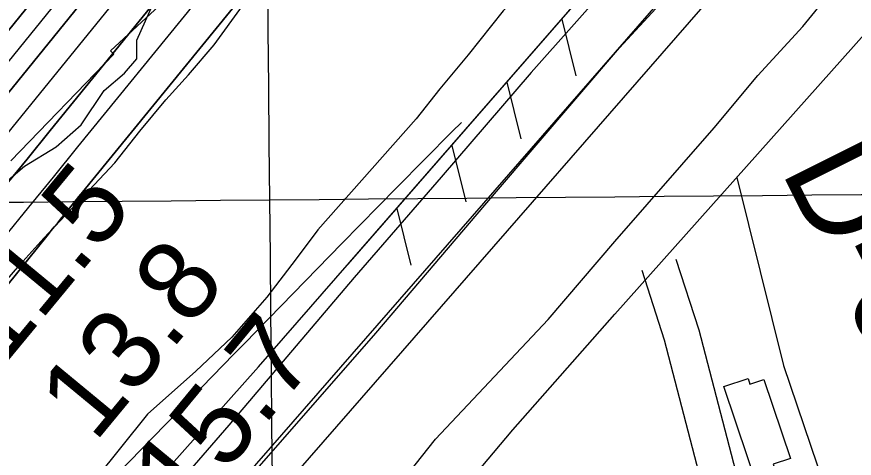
# Model space of a CAD drawing. Extents: x 3598634 to 3636690, y 517270 to 542944.
# Drawn here: x 3607864 to 3608565, y 528569 to 528938 of the extents above; entities that cross this region are included whole.
import ezdxf

# ---------------------------------------------------------------- set-up
doc = ezdxf.new("R2010")
doc.units = 0
for name, color, linetype in [('V-BLDG-OTLN', 7, 'Continuous'), ('V-FLOD-BASE', 7, 'Continuous'), ('V-GRID-MAJR', 7, 'Continuous'), ('V-LEVE-TOET', 7, 'Continuous'), ('V-RIVR-EDGE', 7, 'Continuous'), ('V-RIVR-RANG', 7, 'Continuous'), ('V-RIVR-RANG-IDEN', 7, 'Continuous'), ('V-ROAD-CNTR', 7, 'Continuous'), ('V-RRAP-FSHR', 7, 'Continuous'), ('V-RRAP-RVMT', 7, 'Continuous'), ('V-SITE-VEGE', 7, 'Continuous'), ('V-SURV-LINE', 7, 'Continuous'), ('V-TOPO-DPTH', 7, 'Continuous'), ('V-TOPO-MINR', 7, 'Continuous'), ('V-TOPO-WATR', 7, 'Continuous')]:
    doc.layers.add(name, color=color, linetype=linetype)

msp = doc.modelspace()

# ---------------------------------------------------------------- linework, layer by layer
at = {"layer": 'V-BLDG-OTLN'}
msp.add_lwpolyline([(3608489.164, 528634.588), (3608511.44, 528568.495), (3608496.877, 528563.586), (3608503.15, 528544.98), (3608485.9280000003, 528539.178), (3608455.8140000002, 528628.52), (3608475.948, 528635.307), (3608477.5130000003, 528630.662)], close=True, dxfattribs=at)
at = {"layer": 'V-FLOD-BASE'}
msp.add_lwpolyline([(3608057.5300000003, 528550.9130000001), (3608164.435, 528673.187), (3608262.2660000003, 528787.826), (3608368.484, 528912.1900000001), (3608466.29, 529018.471), (3608577.392, 529146.306), (3608670.332, 529256.082), (3608736.005, 529328.328), (3608865.98, 529479.787), (3608928.157, 529547.863), (3609005.674, 529621.468), (3609041.299, 529658.281), (3609167.019, 529783.983), (3609227.077, 529840.922)], dxfattribs=at)
at = {"layer": 'V-GRID-MAJR'}
for points in [[(3608130.468, 522726.087), (3608075.829, 528784.895), (3608021.174, 534845.634), (3607966.518, 540906.389), (3607966.501, 540908.307)], [(3602797.865, 528737.682), (3608075.829, 528784.895), (3613353.788, 528832.875), (3618631.739, 528881.623), (3623909.683, 528931.139), (3629187.62, 528981.4230000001), (3634465.549, 529032.474), (3634465.5500000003, 529032.474)]]:
    msp.add_spline(points, degree=3, dxfattribs=at)
at = {"layer": 'V-LEVE-TOET'}
for points in [[(3609179.066, 529856.382), (3609077.804, 529759.86), (3609000.984, 529686.253), (3608908.107, 529599.458), (3608868.9960000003, 529561.265), (3608835.45, 529520.268), (3608770.453, 529441.058), (3608694.98, 529351.427), (3608662.1380000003, 529313.215), (3608630.699, 529279.178), (3608596.457, 529238.185), (3608544.745, 529177.042), (3608478.363, 529100.621), (3608366.5670000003, 528972.789), (3608294.6, 528891.508), (3608219.131, 528803.968)], [(3608107.384, 528449.088), (3608214.329, 528584.594), (3608308.637, 528684.617), (3608364.539, 528749.925), (3608447.688, 528845.104), (3608484.0300000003, 528888.878), (3608521.756, 528929.863), (3608569.282, 528988.231), (3608667.838, 529113.314), (3608718.165, 529177.247), (3608772.665, 529239.076), (3608802.713, 529273.814), (3608860.69, 529334.24), (3608893.544, 529376.632), (3608927.0840000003, 529414.841), (3608971.796, 529463.4670000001), (3609015.1010000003, 529507.223), (3609104.504, 529597.509), (3609149.214, 529645.438), (3609180.649, 529678.081)], [(3608219.131, 528803.968), (3608146.46, 528719.902), (3608041.639, 528596.229), (3607974.559, 528519.112)]]:
    msp.add_lwpolyline(points, dxfattribs=at)
at = {"layer": 'V-RIVR-EDGE'}
for points in [[(3607896.9930070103, 528829.1822676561), (3607918.050327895, 528847.7403245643), (3607937.3319151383, 528876.5083251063), (3607954.176584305, 528890.8745122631), (3607964.4117631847, 528902.8557362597), (3607964.450358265, 528918.4641332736), (3607978.9382683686, 528950.8459469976), (3607989.1853226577, 528967.6297546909), (3608009.615600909, 528975.3834827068), (3608032.488734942, 528999.9403159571), (3608052.335018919, 529014.2990809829), (3608070.9569061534, 529019.0556474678), (3608083.6007990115, 529034.0325485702), (3608110.7118200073, 529072.9867419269), (3608141.995413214, 529099.9240850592), (3608192.621455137, 529180.2426701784), (3608231.143065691, 529220.969628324), (3608259.456217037, 529260.5211757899), (3608299.2096464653, 529313.8519472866), (3608325.735188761, 529358.8108546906)], [(3607634.578266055, 528557.2828526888), (3607647.8313884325, 528575.8602071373), (3607658.088833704, 528596.8462755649), (3607670.1294347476, 528610.6240151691), (3607695.3741721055, 528623.1684514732), (3607739.246734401, 528642.8707461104), (3607763.9104463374, 528663.220865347), (3607782.5872573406, 528690.1893814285), (3607813.9569472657, 528751.9454563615), (3607845.2717134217, 528791.489581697), (3607870.5387171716, 528813.0388624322), (3607896.9930070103, 528829.1822676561)]]:
    msp.add_lwpolyline(points, dxfattribs=at)
at = {"layer": 'V-ROAD-CNTR'}
for points in [[(3606832.73929598, 526952.0380697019), (3606973.781013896, 527100.24877328), (3607148.851663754, 527293.0463876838), (3607268.52342441, 527428.8341161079), (3607385.5411903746, 527558.818856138), (3607495.79796986, 527683.4706068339), (3607551.7768579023, 527751.395470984), (3607615.94772956, 527832.2103093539), (3607705.6035502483, 527929.2831152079), (3607806.918347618, 528046.9048799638), (3607941.5770783, 528200.235573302), (3608081.9227976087, 528357.7092583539), (3608279.135403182, 528592.4517888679), (3608364.492232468, 528689.307595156), (3608525.0129114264, 528869.3482350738), (3608605.4767504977, 528959.8330541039), (3608701.50055845, 529074.4648248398), (3608833.107295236, 529225.3725230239), (3608919.0001234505, 529316.1323415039), (3609050.5348603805, 529472.9320279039), (3609139.7006820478, 529575.1978233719), (3609208.81954381, 529647.870678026)], [(3608466.4920284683, 528803.7113663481), (3608505.692950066, 528646.338681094), (3608601.7287579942, 528362.269249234), (3608772.481416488, 527825.480322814)], [(3608415.530130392, 528735.1725034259), (3608434.6610921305, 528676.1496214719), (3608465.3830306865, 528557.9068579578), (3608506.948947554, 528426.4981207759), (3608525.973909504, 528355.965261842), (3608533.1488951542, 528306.5663606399), (3608536.582888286, 528256.783460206), (3608541.2408789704, 528212.94154789), (3608549.5638623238, 528173.7936261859), (3608569.869821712, 528109.3447550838), (3608666.4776284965, 527809.824354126), (3608789.826381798, 527407.3961589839), (3608865.133231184, 527174.4286249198), (3608901.88515768, 527053.927865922)], [(3608386.9921874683, 528725.9225219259), (3608405.8491497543, 528667.74563828), (3608436.5430883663, 528549.604874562), (3608478.15100515, 528418.0641376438), (3608496.541968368, 528349.8812740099), (3608503.296954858, 528303.372367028), (3608506.6929480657, 528254.165465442), (3608511.572938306, 528208.225557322), (3608520.517920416, 528166.149641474), (3608541.2878788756, 528100.2327733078), (3608637.859685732, 527800.8243721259), (3608761.21043903, 527398.3861770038), (3608836.511288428, 527165.4386429), (3608873.1892150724, 527045.175883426)]]:
    msp.add_lwpolyline(points, dxfattribs=at)
at = {"layer": 'V-RRAP-FSHR'}
for p, q in [((3608320.009321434, 528936.067101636), (3608331.7782978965, 528888.6761964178)), ((3608274.035413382, 528883.2812072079), (3608285.804389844, 528835.8893019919)), ((3608228.0615053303, 528830.4943127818), (3608239.830481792, 528783.103407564)), ((3608182.0875972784, 528777.7084183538), (3608193.85657374, 528730.317513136))]:
    msp.add_line(p, q, dxfattribs=at)
for points in [[(3605375.168211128, 525433.7531062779), (3605455.95704955, 525580.4988127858), (3605630.7317, 525877.6072185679), (3605746.7854678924, 526080.3428130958), (3605800.6313602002, 526159.0466556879), (3605867.2622269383, 526231.5935105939), (3605948.3560647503, 526309.6363545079), (3606191.901577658, 526556.4788608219), (3606564.79483187, 526949.5770746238), (3606877.8712057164, 527278.8654160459), (3607054.81385183, 527479.4700148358), (3607380.1992010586, 527856.781260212), (3607669.24262297, 528199.3665750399), (3608066.4648285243, 528644.9536838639), (3608475.6160102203, 529114.730744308), (3608696.8345677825, 529376.9982197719), (3608831.88529768, 529536.017901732), (3608922.7861158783, 529648.802676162), (3609014.7149320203, 529727.84851807), (3609124.1937130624, 529832.0493096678), (3609276.097409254, 529976.2740212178)], [(3608141.3756787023, 528730.964511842), (3608475.6160102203, 529114.730744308), (3608696.8345677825, 529376.9982197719), (3608831.88529768, 529536.017901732), (3608833.777293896, 529538.3658970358)]]:
    msp.add_lwpolyline(points, dxfattribs=at)
at = {"layer": 'V-RRAP-RVMT'}
for p, q in [((3607942.5896928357, 528909.4765619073), (3608000.042151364, 528963.0483299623)), ((3607859.168962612, 528817.6532788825), (3607945.306657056, 528906.851359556)), ((3607945.306657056, 528906.851359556), (3607942.5896928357, 528909.4765619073))]:
    msp.add_line(p, q, dxfattribs=at)
at = {"layer": 'V-SITE-VEGE'}
for points in [[(3608593.151, 529300.178), (3608537.2490000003, 529235.566), (3608510.007, 529207.086), (3608481.363, 529175.829), (3608451.3310000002, 529146.664), (3608430.37, 529123.042), (3608407.326, 529101.518), (3608384.972, 529077.902), (3608363.31, 529052.89), (3608321.369, 528998.686), (3608300.406, 528974.37), (3608271.066, 528943.111), (3608241.708, 528906.282), (3608217.95, 528877.794), (3608198.377, 528852.778), (3608115.9280000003, 528759.686), (3608097.752, 528735.362), (3608073.285, 528703.395), (3608043.937, 528670.047), (3608013.909, 528641.578), (3607973.412, 528605.476), (3607929.378, 528550.581)], [(3607845.549, 528706.131), (3607866.5130000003, 528730.447), (3607886.772, 528752.678), (3607904.935, 528772.1240000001), (3607920.3030000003, 528788.1), (3607946.151, 528815.885), (3607967.1210000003, 528842.294), (3607988.787, 528868.6950000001), (3608007.651, 528889.535), (3608029.31, 528914.55), (3608053.083, 528947.213)]]:
    msp.add_lwpolyline(points, dxfattribs=at)
at = {"layer": 'V-SURV-LINE'}
for points in [[(3607846.344686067, 528313.6251302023), (3608742.972105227, 529342.319632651)], [(3608765.5791539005, 529322.5985397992), (3607868.951734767, 528293.9040373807)]]:
    msp.add_lwpolyline(points, dxfattribs=at)
at = {"layer": 'V-TOPO-DPTH'}
for points in [[(3607050.110421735, 527933.8661143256), (3607754.6678173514, 528800.4477853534), (3607773.1231306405, 528823.1621606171), (3607791.5686676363, 528845.8844668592), (3607809.999540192, 528868.6186695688), (3607828.420636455, 528891.360803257), (3608108.5226418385, 529237.3945285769), (3608193.270411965, 529341.3823736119), (3608278.475807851, 529444.99132357), (3608364.367642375, 529548.0319309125), (3608450.7171026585, 529650.6936431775), (3608605.4413867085, 529833.411271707), (3608614.8399220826, 529844.369931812), (3608624.329041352, 529855.2485710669), (3608633.9540364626, 529866.0071790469), (3608643.669615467, 529876.6857661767), (3609104.282173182, 530376.6107843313)], [(3609104.282173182, 530376.6107843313), (3608643.669615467, 529876.6857661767), (3608633.9540364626, 529866.0071790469), (3608624.329041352, 529855.2485710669), (3608614.8399220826, 529844.369931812), (3608605.4413867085, 529833.411271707), (3608450.7171026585, 529650.6936431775), (3608364.367642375, 529548.0319309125), (3608278.475807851, 529444.99132357), (3608193.270411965, 529341.3823736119), (3608108.5226418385, 529237.3945285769), (3607828.420636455, 528891.360803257), (3607809.999540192, 528868.6186695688), (3607791.5686676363, 528845.8844668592), (3607773.1231306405, 528823.1621606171), (3607754.6678173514, 528800.4477853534), (3607050.110421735, 527933.8661143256)], [(3608991.262616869, 530147.8676727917), (3608718.8075875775, 529843.8314700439), (3608702.0593536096, 529824.9491268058), (3608685.4407747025, 529805.9545085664), (3608669.0166783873, 529786.7914778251), (3608652.722237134, 529767.5161720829), (3608514.674114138, 529602.5153722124), (3608429.6663916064, 529500.4793089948), (3608344.943345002, 529398.2084138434), (3608260.647312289, 529295.5852707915), (3608176.635955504, 529192.7272958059), (3607892.148238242, 528842.9338263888), (3607872.700147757, 528819.0185201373), (3607853.2538833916, 528795.1017292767), (3607833.8103582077, 528771.182711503), (3607814.3686591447, 528747.262209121), (3607476.376953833, 528331.3583664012)], [(3607476.376953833, 528331.3583664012), (3607814.3686591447, 528747.262209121), (3607833.8103582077, 528771.182711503), (3607853.2538833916, 528795.1017292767), (3607872.700147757, 528819.0185201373), (3607892.148238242, 528842.9338263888), (3608176.635955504, 529192.7272958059), (3608260.647312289, 529295.5852707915), (3608344.943345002, 529398.2084138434), (3608429.6663916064, 529500.4793089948), (3608514.674114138, 529602.5153722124), (3608652.722237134, 529767.5161720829), (3608669.0166783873, 529786.7914778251), (3608685.4407747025, 529805.9545085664), (3608702.0593536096, 529824.9491268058), (3608718.8075875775, 529843.8314700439), (3608991.262616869, 530147.8676727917)], [(3608692.0499146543, 529894.310394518), (3608646.0571142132, 529844.3928552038), (3608644.3113008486, 529842.4744016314), (3608642.5815031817, 529840.5417904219), (3608640.875729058, 529838.5879427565), (3608639.1859706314, 529836.6199374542), (3608610.975637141, 529803.3503869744), (3608595.2558213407, 529784.6846881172), (3608579.620121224, 529765.9492680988), (3608564.110594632, 529747.1092663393), (3608548.685183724, 529728.1995434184), (3607821.8677533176, 528831.0740898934), (3607819.144475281, 528827.7105861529), (3607816.4225722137, 528824.3459707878), (3607813.7027316, 528820.9796879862), (3607810.984265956, 528817.61229356), (3607746.463470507, 528737.6395229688), (3607711.520787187, 528694.2567081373), (3607676.6249686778, 528650.8362916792), (3607641.799447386, 528607.3594727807), (3607607.020790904, 528563.8450522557)], [(3607607.020790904, 528563.8450522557), (3607641.799447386, 528607.3594727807), (3607676.6249686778, 528650.8362916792), (3607711.520787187, 528694.2567081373), (3607746.463470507, 528737.6395229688), (3607810.984265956, 528817.61229356), (3607813.7027316, 528820.9796879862), (3607816.4225722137, 528824.3459707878), (3607819.144475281, 528827.7105861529), (3607821.8677533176, 528831.0740898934), (3608548.685183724, 529728.1995434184), (3608564.110594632, 529747.1092663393), (3608579.620121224, 529765.9492680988), (3608595.2558213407, 529784.6846881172), (3608610.975637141, 529803.3503869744), (3608639.1859706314, 529836.6199374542), (3608640.875729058, 529838.5879427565), (3608642.5815031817, 529840.5417904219), (3608644.3113008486, 529842.4744016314), (3608646.0571142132, 529844.3928552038), (3608692.0499146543, 529894.310394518)], [(3608826.278553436, 529889.7496636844), (3608805.0948457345, 529867.4214339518), (3608784.247844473, 529844.7785133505), (3608763.6253141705, 529821.9257988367), (3608724.162120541, 529777.5310744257), (3608723.444853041, 529776.7138432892), (3608722.7345501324, 529775.8906787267), (3608721.3418026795, 529774.2206158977), (3607992.342167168, 528881.1336073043), (3607976.182451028, 528861.3303280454), (3607960.0268139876, 528841.5237226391), (3607943.8772955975, 528821.7121280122), (3607927.731856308, 528801.8972072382), (3607900.6113318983, 528768.6023214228), (3607898.0316686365, 528765.4303601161), (3607895.455278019, 528762.2557470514), (3607892.88379637, 528759.0771563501), (3607890.315587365, 528755.8959138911), (3607830.1698473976, 528681.2754461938), (3607797.532199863, 528640.781193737), (3607764.895854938, 528600.2858915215), (3607732.261463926, 528559.7890146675)]]:
    msp.add_lwpolyline(points, dxfattribs=at)
at = {"layer": 'V-TOPO-MINR'}
for points in [[(3607269.9346052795, 528037.4466619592), (3607833.1789492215, 528728.441475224), (3607853.695733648, 528753.6155649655), (3607874.209999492, 528778.7917066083), (3607894.720487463, 528803.9709261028), (3607915.2284568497, 528829.1521974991), (3608012.971921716, 528949.1875763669), (3608082.5213329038, 529034.2464083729), (3608152.2995331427, 529119.1163572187), (3608222.420916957, 529203.7029813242), (3608292.771089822, 529288.1007222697), (3608697.7320062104, 529771.9288514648), (3608703.7902030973, 529779.1057189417), (3608709.8880741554, 529786.2484280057), (3608716.04545647, 529793.3398994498), (3608722.2425129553, 529800.3972124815), (3609349.791717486, 530509.062902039)], [(3607050.110421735, 527933.8661143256), (3607754.6678173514, 528800.4477853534), (3607773.1231306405, 528823.1621606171), (3607791.5686676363, 528845.8844668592), (3607809.999540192, 528868.6186695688), (3607828.420636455, 528891.360803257), (3608108.5226418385, 529237.3945285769), (3608193.270411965, 529341.3823736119), (3608278.475807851, 529444.99132357), (3608364.367642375, 529548.0319309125), (3608450.7171026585, 529650.6936431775), (3608605.4413867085, 529833.411271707), (3608614.8399220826, 529844.369931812), (3608624.329041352, 529855.2485710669), (3608633.9540364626, 529866.0071790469), (3608643.669615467, 529876.6857661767), (3609104.282173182, 530376.6107843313)], [(3607538.861497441, 528507.8470592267), (3607788.102173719, 528815.6048933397), (3607796.0217690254, 528825.383855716), (3607803.941370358, 528835.1628132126), (3607811.8609807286, 528844.9417633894), (3607819.7805971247, 528854.7207086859), (3608327.2406076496, 529481.3191128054), (3608377.5500924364, 529543.0180431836), (3608428.1322050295, 529604.4911170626), (3608479.123259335, 529665.6254061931), (3608530.386941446, 529726.5338388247), (3608622.313038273, 529835.0183809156), (3608627.857922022, 529841.4799990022), (3608633.4557975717, 529847.8947890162), (3608639.1331608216, 529854.2393369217), (3608644.863515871, 529860.5370567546), (3608795.867747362, 530024.4293374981)], [(3607607.020790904, 528563.8450522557), (3607641.799447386, 528607.3594727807), (3607676.6249686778, 528650.8362916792), (3607711.520787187, 528694.2567081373), (3607746.463470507, 528737.6395229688), (3607810.984265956, 528817.61229356), (3607813.7027316, 528820.9796879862), (3607816.4225722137, 528824.3459707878), (3607819.144475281, 528827.7105861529), (3607821.8677533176, 528831.0740898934), (3608548.685183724, 529728.1995434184), (3608564.110594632, 529747.1092663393), (3608579.620121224, 529765.9492680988), (3608595.2558213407, 529784.6846881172), (3608610.975637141, 529803.3503869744), (3608639.1859706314, 529836.6199374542), (3608640.875729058, 529838.5879427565), (3608642.5815031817, 529840.5417904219), (3608644.3113008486, 529842.4744016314), (3608646.0571142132, 529844.3928552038), (3608692.0499146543, 529894.310394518)], [(3607616.821328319, 528543.0276400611), (3607659.8796647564, 528596.736166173), (3607703.0201507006, 528650.3787293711), (3607746.2154029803, 528703.9773172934), (3607777.6016978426, 528742.8618854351), (3607805.1597452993, 528776.9731712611), (3607832.737616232, 528811.0684085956), (3607860.345222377, 528845.1395731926), (3607887.9726519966, 528879.1946892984), (3608477.194766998, 529604.8556301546), (3608507.459859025, 529641.9636581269), (3608537.8320823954, 529678.9834015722), (3608568.365002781, 529715.8707182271), (3608599.0050545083, 529752.6697503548), (3608607.7246853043, 529763.0959346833), (3608634.275550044, 529794.4497895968), (3608661.080028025, 529825.5825634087), (3608688.2649258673, 529856.3837155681), (3608715.70343695, 529886.9637866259)], [(3607732.261463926, 528559.7890146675), (3607764.895854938, 528600.2858915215), (3607797.532199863, 528640.781193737), (3607830.1698473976, 528681.2754461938), (3607890.315587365, 528755.8959138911), (3607892.88379637, 528759.0771563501), (3607895.455278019, 528762.2557470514), (3607898.0316686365, 528765.4303601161), (3607900.6113318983, 528768.6023214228), (3607927.731856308, 528801.8972072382), (3607943.8772955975, 528821.7121280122), (3607960.0268139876, 528841.5237226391), (3607976.182451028, 528861.3303280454), (3607992.342167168, 528881.1336073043), (3608721.3418026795, 529774.2206158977), (3608722.7345501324, 529775.8906787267), (3608723.444853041, 529776.7138432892), (3608724.162120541, 529777.5310744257), (3608763.6253141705, 529821.9257988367), (3608784.247844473, 529844.7785133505), (3608805.0948457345, 529867.4214339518), (3608826.278553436, 529889.7496636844)], [(3607755.8607184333, 528358.0040238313), (3608018.8785887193, 528628.1834398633), (3608027.7888323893, 528637.3325297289), (3608036.7015835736, 528646.4791751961), (3608045.618096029, 528655.6221540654), (3608054.537115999, 528664.762688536), (3608136.164790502, 528748.3832732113), (3608182.2045593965, 528795.2588731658), (3608228.4344828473, 528841.94501929), (3608236.0611671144, 528849.5531447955)]]:
    msp.add_lwpolyline(points, dxfattribs=at)
at = {"layer": 'V-TOPO-WATR'}
msp.add_lwpolyline([(3607476.376953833, 528331.3583664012), (3607814.3686591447, 528747.262209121), (3607833.8103582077, 528771.182711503), (3607853.2538833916, 528795.1017292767), (3607872.700147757, 528819.0185201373), (3607892.148238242, 528842.9338263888), (3608176.635955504, 529192.7272958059), (3608260.647312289, 529295.5852707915), (3608344.943345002, 529398.2084138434), (3608429.6663916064, 529500.4793089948), (3608514.674114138, 529602.5153722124), (3608652.722237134, 529767.5161720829), (3608669.0166783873, 529786.7914778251), (3608685.4407747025, 529805.9545085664), (3608702.0593536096, 529824.9491268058), (3608718.8075875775, 529843.8314700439), (3608991.262616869, 530147.8676727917)], dxfattribs=at)

# ---------------------------------------------------------------- texts
at = {"layer": 'V-RIVR-RANG'}
for s, p in [('11.5', (3607852.1406342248, 528644.3807617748)), ('13.8', (3607929.4076342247, 528580.8987617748)), ('15.7', (3608006.673634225, 528517.4177617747))]:
    msp.add_text(s, height=67, rotation=50.44832571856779, dxfattribs=at).set_placement(p)
at = {"layer": 'V-RIVR-RANG-IDEN'}
msp.add_text('D-070', height=83.00000000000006, rotation=296.6053540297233, dxfattribs=at).set_placement((3608502.976803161, 528809.8389706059))

doc.saveas('drawing.dxf')
